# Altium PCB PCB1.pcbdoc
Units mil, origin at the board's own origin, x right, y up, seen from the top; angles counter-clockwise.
Board outline 3779.53 x 2362.2 mil, 2 copper layers (Top Layer, Bottom Layer), stack 62.206 mil thick; 19 components, 19 nets, 99 pads, 0 vias.
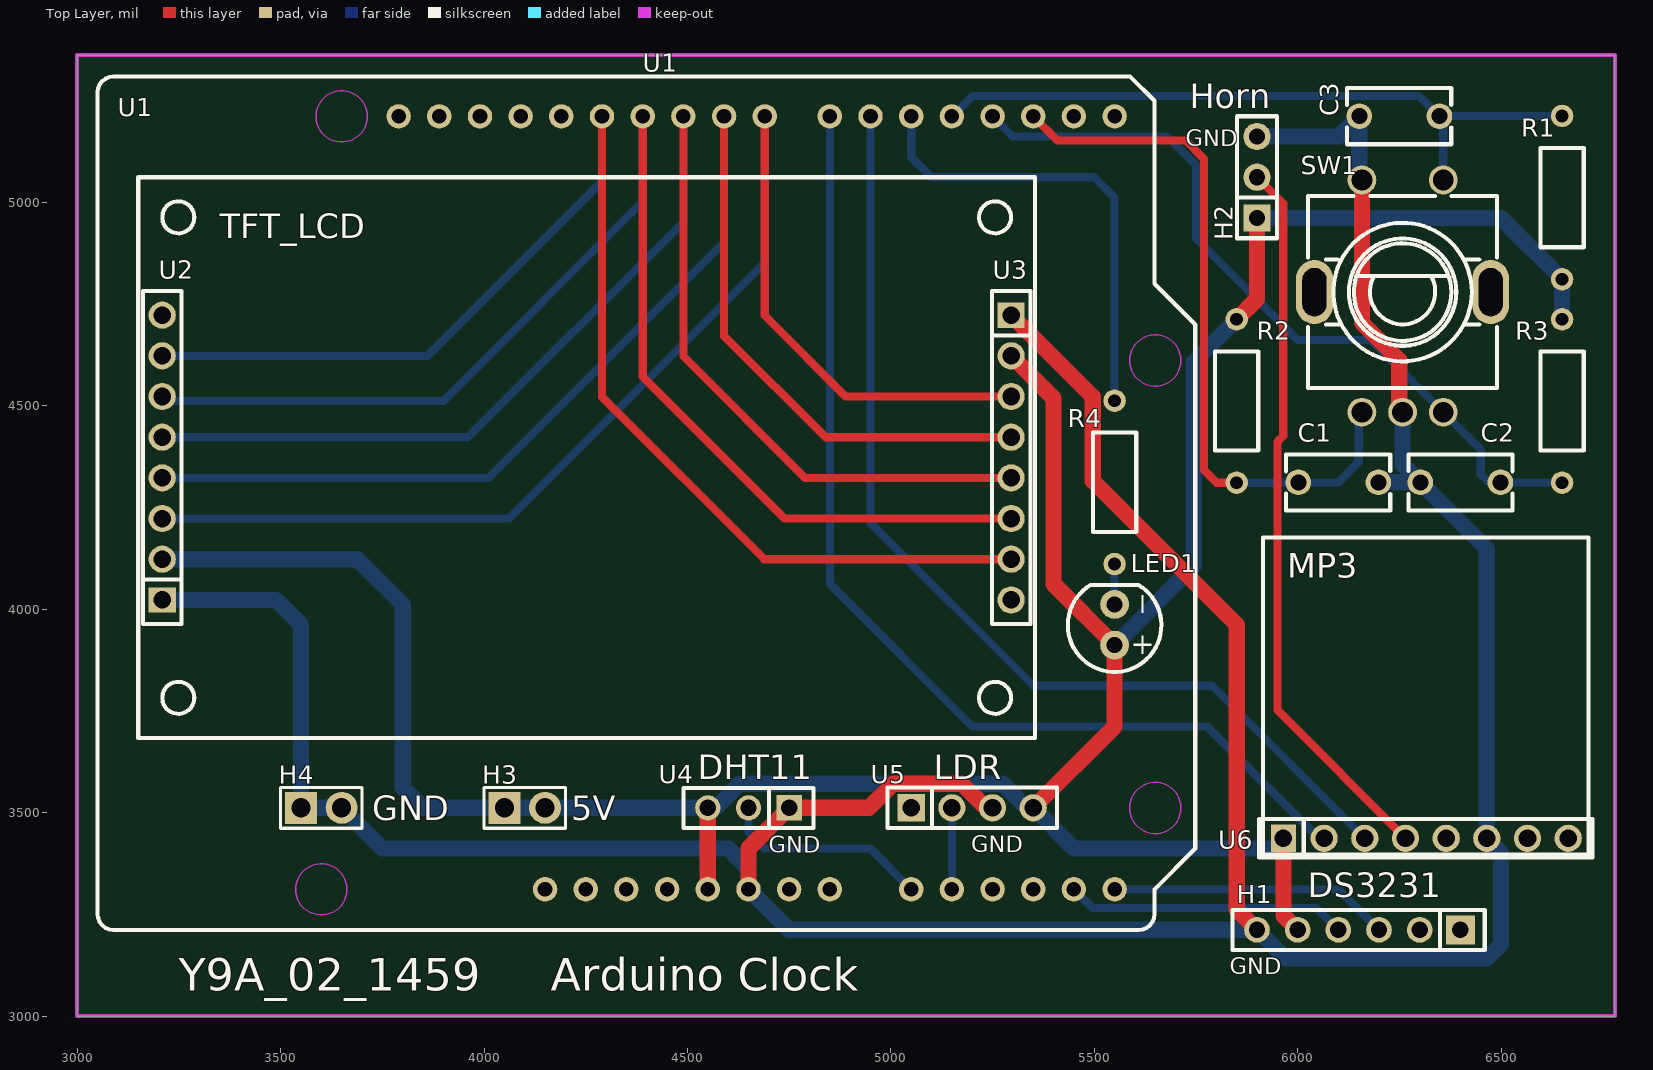
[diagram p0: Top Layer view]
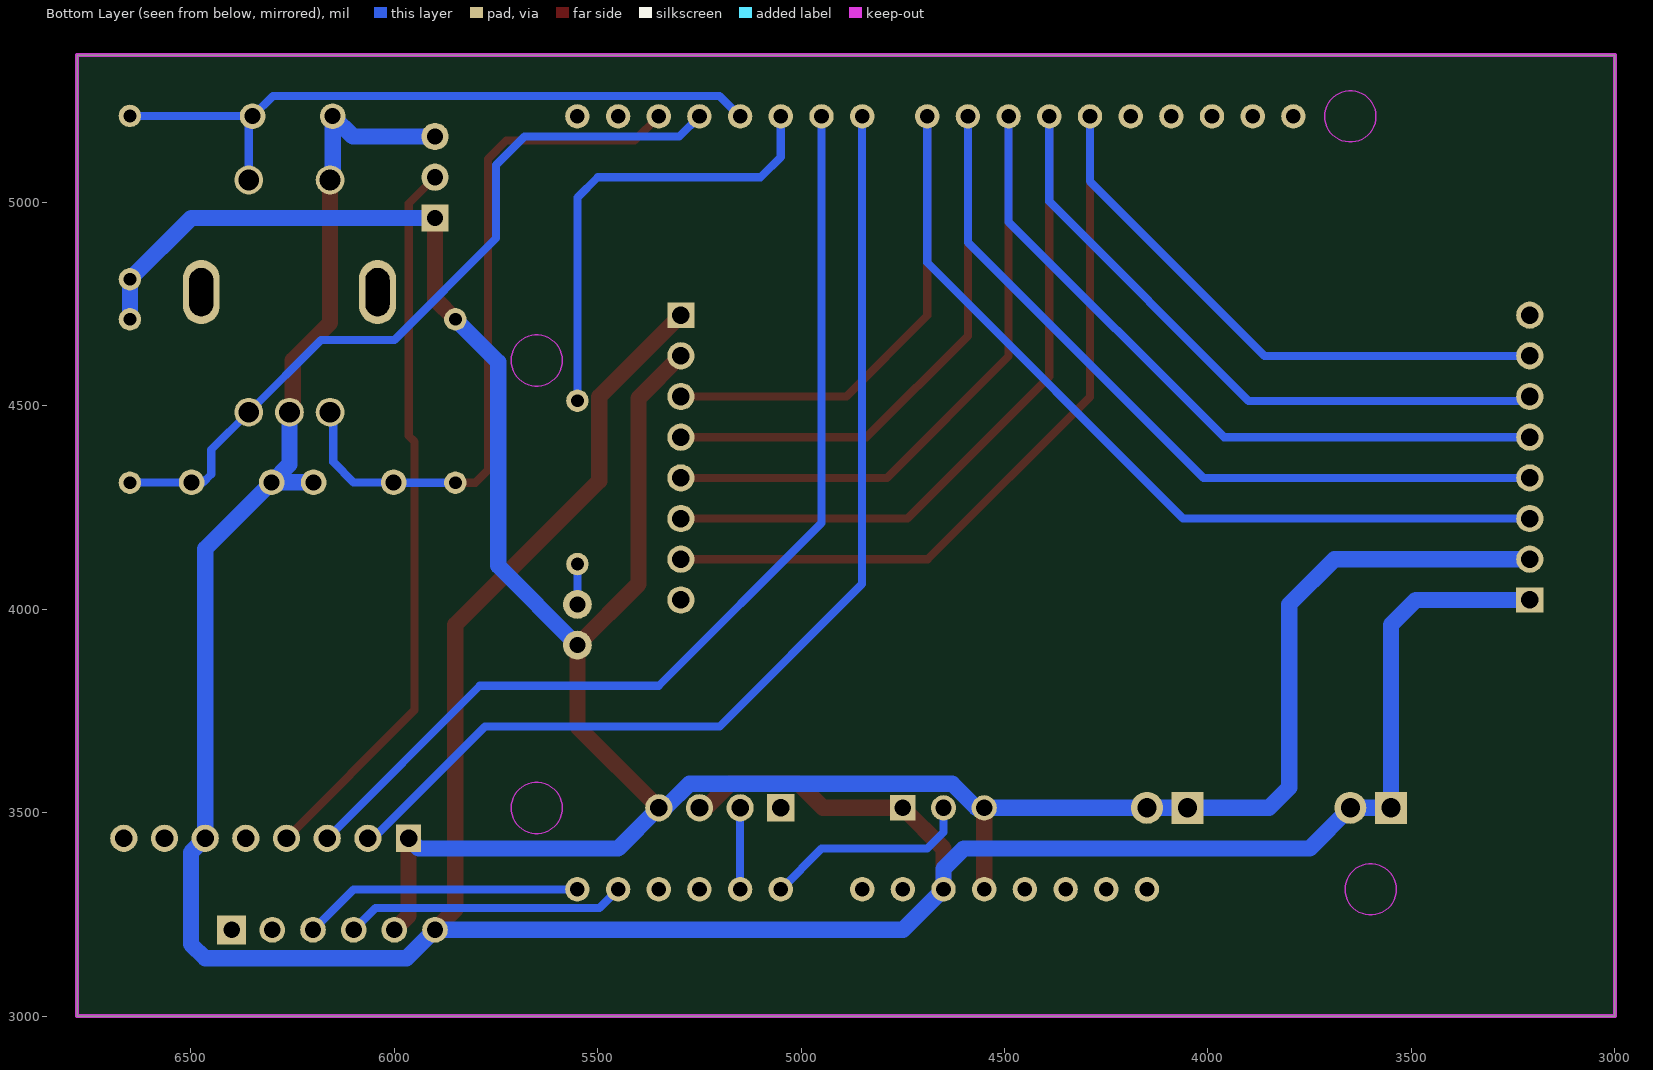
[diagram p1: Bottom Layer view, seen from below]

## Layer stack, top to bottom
Top Solder Mask Layer: solder mask 0.394, Dk 3.3
Top Layer: signal copper 1.379
Dielectric1: surface 59.449, FR4, Dk 4.5
Bottom Layer: signal copper 1.378
Bottom Solder Mask Layer: solder mask 0.394, Dk 3.3

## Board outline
3000,5362.2 6779.53,5362.2 6779.53,3000 3000,3000

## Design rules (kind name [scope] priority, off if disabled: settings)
BoardOutlineClearance copperThickness1oz [All] p0: genericclearance=10 ignorepadtopadclearanceinfootprint=FALSE except(0: Arc-SplitContinuation Track-SplitContinuation SMDPad-SplitContinuation THPad-SplitContinuation Via-SplitContinuation Fill-SplitContinuation Poly-SplitContinuation Region-SplitContinuation Text-SplitContinuation)
BoardOutlineClearance copperThickness2oz [All] p0: genericclearance=10 ignorepadtopadclearanceinfootprint=FALSE except(0: Arc-SplitContinuation Track-SplitContinuation SMDPad-SplitContinuation THPad-SplitContinuation Via-SplitContinuation Fill-SplitContinuation Poly-SplitContinuation Region-SplitContinuation Text-SplitContinuation)
BoardOutlineClearance otherClearance [All] p0: genericclearance=10 ignorepadtopadclearanceinfootprint=FALSE except(0: Arc-SplitContinuation Track-SplitContinuation SMDPad-SplitContinuation THPad-SplitContinuation Via-SplitContinuation Fill-SplitContinuation Poly-SplitContinuation Region-SplitContinuation Text-SplitContinuation)
Clearance copperThickness1oz [All] p1: gap=7 ignorepadtopadclearanceinfootprint=FALSE
Clearance copperThickness2oz [All] p1: gap=7 ignorepadtopadclearanceinfootprint=FALSE
Clearance otherClearance [All] p1: gap=7 ignorepadtopadclearanceinfootprint=FALSE
DiffPairsRouting differentialPair [All] p1: maxuncoupledlength=10 minlimit=6 maxlimit=Infinity mostfreqgap=6 toplayer_minwidth=5 toplayer_prefwidth=10 toplayer_maxwidth=100 bottomlayer_minwidth=5 bottomlayer_prefwidth=10 bottomlayer_maxwidth=100
PasteMaskExpansion pasteMaskExpansion [All] p1: expansion=0
PlaneConnect innerPlane [All] p1: planeconnectstyle=Relief reliefexpansion=20 reliefentries=4 reliefconductorwidth=10 reliefairgap=10
PolygonConnect copperRegion [All] p1: connectstyle=Relief reliefentries=4 reliefconductorwidth=10 polygonreliefangle="90 Angle" airgapwidth=10
RoutingVias viaSize [All] p1: viastyle="Through Hole" holewidth=12.0078 minholewidth=11.811 maxholewidth=248.0314 width=12.0078 minwidth=11.811 maxwidth=248.0314
SolderMaskExpansion solderMaskExpansion [IsVia] p1: useseparateexpansions=TRUE expansion=-1000 expansionbottom=-1000
SolderMaskExpansion solderMaskExpansion [All] p2: useseparateexpansions=TRUE expansion=2 expansionbottom=2
Width copperThickness1oz [All] p1: maxlimit=100 minlimit=5 preferedwidth=10
Width copperThickness2oz [All] p1: maxlimit=100 minlimit=8 preferedwidth=10

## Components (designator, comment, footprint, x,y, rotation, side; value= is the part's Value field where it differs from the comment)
C1 "100nF" CAP-TH_L6.5-W3.5-P5.00-D0.5 6100,4312.2 r180 top
C2 "100nF" CAP-TH_L6.5-W3.5-P5.00-D0.5 6400,4312.2 r0 top
C3 "100nF" CAP-TH_L6.5-W3.5-P5.00-D0.5 6250,5212.2 r180 top
H1 "PM254V-11-06-H85" HDR-TH_6P-P2.54-V-F 6150,3212.2 r180 top
H2 "PZ254V-11-03P" HDR-TH_3P-P2.54-V-M_PZ254V-11-03P 5900,5062.2 r90 top
H3 "PZ254V-11-02P" HDR-TH_2P-P2.54-V-M 4100,3512.2 r0 top
H4 "PZ254V-11-02P" HDR-TH_2P-P2.54-V-M 3600,3512.2 r0 top
LED1 "XL-502SURD" LED-TH_BD5.9-P2.54-RD_RED 5550,3962.2 r270 top
R1 "10kΩ" RES-TH_BD2.7-L6.2-P10.20-D0.4 6650,5012.2 r90 top
R2 "10kΩ" RES-TH_BD2.7-L6.2-P10.20-D0.4 5850,4512.2 r270 top
R3 "10kΩ" RES-TH_BD2.7-L6.2-P10.20-D0.4 6650,4512.2 r270 top
R4 "10kΩ" RES-TH_BD2.7-L6.2-P10.20-D0.4 5550,4312.2 r90 top
SW1 "EC11E15244B2" SW-TH_EC11XXXXXXXX 6257.87,4770.08 r0 top
U1 "" "Arduino UNO" 3050,5312.2 r0 top
U2 "PM254-1-08-Z-8.5" HDR-TH_8P-P2.54-V-F 3209.06,4373.23 r90 top
U3 "PM254-1-08-Z-8.5" HDR-TH_8P-P2.54-V-F 5295.67,4373.23 r270 top
U4 "PM254V-11-03-H85" HDR-TH_3P-P2.54-V-F 4650,3512.2 r180 top
U5 "2.54-1*4P母" HDR-TH_4P-P2.54-V-F 5200,3512.2 r0 top
U6 "PM254-1-08-Z-8.5" HDR-TH_8P-P2.54-V-F 6315,3437.2 r0 top

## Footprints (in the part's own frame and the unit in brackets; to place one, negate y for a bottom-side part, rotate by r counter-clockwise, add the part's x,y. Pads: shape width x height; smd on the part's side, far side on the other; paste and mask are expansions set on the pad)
"Arduino UNO" [mil]
  round 60 hole 36 paste+0 mask+2: 0(2500,-100.4) 1(2400,-100.4) 2(2300,-100.4) 3(2200,-100.4) 4(2100,-100.4) 5(2000,-100.4) 6(1900,-100.4) 7(1800,-100.4) 8(1640,-100.4) 9(1540,-100.4) 10(1440,-100.4) 11(1340,-100.4) 12(1240,-100.4) 13(1140,-100.4) 14(1040,-100.4) 15(940,-100.4) 16(840,-100.4) 17(740,-100.4) 18(1100,-2000.4) 19(1200,-2000.4) 20(1300,-2000.4) 21(1400,-2000.4) 22(1500,-2000.4) 23(1600,-2000.4) 24(1700,-2000.4) 25(1800,-2000.4) 26(2000,-2000.4) 27(2100,-2000.4) 28(2200,-2000.4) 29(2300,-2000.4) 30(2400,-2000.4) 31(2500,-2000.4)
  Board Outline Layer circle w0.1: c550,-2000.4 r62.99
  Board Outline Layer circle w0.1: c600,-100.4 r62.99
  Board Outline Layer circle w0.1: c2600,-700.4 r62.99
  Board Outline Layer circle w0.1: c2600,-1800.4 r62.99
  Board Outline Layer region: 612.99,-2000.4 606.75,-2027.73 589.27,-2049.65 564.02,-2061.81 535.98,-2061.81 510.73,-2049.65 493.25,-2027.73 487.01,-2000.4 487.01,-2000.4 493.25,-1973.07 510.73,-1951.15 535.98,-1938.99 564.02,-1938.99 589.27,-1951.15 606.75,-1973.07 612.99,-2000.4
  Board Outline Layer region: 612.99,-2000.4 606.75,-2027.73 589.27,-2049.65 564.02,-2061.81 535.98,-2061.81 510.73,-2049.65 493.25,-2027.73 487.01,-2000.4 487.01,-2000.4 493.25,-1973.07 510.73,-1951.15 535.98,-1938.99 564.02,-1938.99 589.27,-1951.15 606.75,-1973.07 612.99,-2000.4
  Board Outline Layer region: 662.99,-100.4 656.75,-127.73 639.27,-149.65 614.02,-161.81 585.98,-161.81 560.73,-149.65 543.25,-127.73 537.01,-100.4 537.01,-100.4 543.25,-73.07 560.73,-51.15 585.98,-38.99 614.02,-38.99 639.27,-51.15 656.75,-73.07 662.99,-100.4
  Board Outline Layer region: 662.99,-100.4 656.75,-127.73 639.27,-149.65 614.02,-161.81 585.98,-161.81 560.73,-149.65 543.25,-127.73 537.01,-100.4 537.01,-100.4 543.25,-73.07 560.73,-51.15 585.98,-38.99 614.02,-38.99 639.27,-51.15 656.75,-73.07 662.99,-100.4
  Board Outline Layer region: 2662.99,-700.4 2656.75,-727.73 2639.27,-749.65 2614.02,-761.81 2585.98,-761.81 2560.73,-749.65 2543.25,-727.73 2537.01,-700.4 2537.01,-700.4 2543.25,-673.07 2560.73,-651.15 2585.98,-638.99 2614.02,-638.99 2639.27,-651.15 2656.75,-673.07 2662.99,-700.4
  Board Outline Layer region: 2662.99,-700.4 2656.75,-727.73 2639.27,-749.65 2614.02,-761.81 2585.98,-761.81 2560.73,-749.65 2543.25,-727.73 2537.01,-700.4 2537.01,-700.4 2543.25,-673.07 2560.73,-651.15 2585.98,-638.99 2614.02,-638.99 2639.27,-651.15 2656.75,-673.07 2662.99,-700.4
  Board Outline Layer region: 2662.99,-1800.4 2656.75,-1827.73 2639.27,-1849.65 2614.02,-1861.81 2585.98,-1861.81 2560.73,-1849.65 2543.25,-1827.73 2537.01,-1800.4 2537.01,-1800.4 2543.25,-1773.07 2560.73,-1751.15 2585.98,-1738.99 2614.02,-1738.99 2639.27,-1751.15 2656.75,-1773.07 2662.99,-1800.4
  Board Outline Layer region: 2662.99,-1800.4 2656.75,-1827.73 2639.27,-1849.65 2614.02,-1861.81 2585.98,-1861.81 2560.73,-1849.65 2543.25,-1827.73 2537.01,-1800.4 2537.01,-1800.4 2543.25,-1773.07 2560.73,-1751.15 2585.98,-1738.99 2614.02,-1738.99 2639.27,-1751.15 2656.75,-1773.07 2662.99,-1800.4
  silkscreen extent 0,-2100 2698,-2
CAP-TH_L6.5-W3.5-P5.00-D0.5 [mm]
  round 1.6 hole 1: 1(-2.499,0) 2(2.499,0)
  silkscreen extent -3.24,-1.75 3.26,1.75
HDR-TH_2P-P2.54-V-M [mm]
  rect 2x2 hole 1.2: 1(-1.27,0)
  round 2 hole 1.2: 2(1.27,0)
  silkscreen extent -2.54,-1.27 2.54,1.27
HDR-TH_3P-P2.54-V-F [mil]
  rect 62x62 hole 40.16: 1(-100,0)
  round 62 hole 40.16: 2(0,0) 3(100,0)
  silkscreen extent -160,-49 160,49
HDR-TH_3P-P2.54-V-M_PZ254V-11-03P [mm]
  rect 1.7x1.7 hole 1.02: 1(-2.54,0)
  round 1.7 hole 1.02: 2(0,0) 3(2.54,0)
  silkscreen extent -3.81,-1.25 3.81,1.25
HDR-TH_4P-P2.54-V-F [mm]
  rect 1.7x1.7 hole 1.1: 1(-3.81,0)
  round 1.7 hole 1.1: 2(-1.27,0) 3(1.27,0) 4(3.81,0)
  silkscreen extent -5.29,-1.27 5.29,1.27
HDR-TH_6P-P2.54-V-F [mm]
  rect 1.8x1.8 hole 1.02: 1(-6.35,0)
  round 1.6 hole 1.02: 2(-3.81,0) 3(-1.27,0) 4(1.27,0) 5(3.81,0) 6(6.35,0)
  silkscreen extent -7.87,-1.25 7.87,1.25
HDR-TH_8P-P2.54-V-F [mm]
  rect 1.575x1.7 hole 1.1: 1(-8.89,0)
  round 1.7 hole 1.1: 2(-6.35,0) 3(-3.81,0) 4(-1.27,0) 5(1.27,0) 6(3.81,0) 7(6.35,0) 8(8.89,0)
  silkscreen extent -10.4,-1.2 10.4,1.2
LED-TH_BD5.9-P2.54-RD_RED [mm]
  round 1.8 hole 1 paste+0 mask+0.05: 1(-1.27,0) 2(1.27,0)
  silkscreen extent -2.49,-2.92 2.94,2.92
RES-TH_BD2.7-L6.2-P10.20-D0.4 [mm]
  round 1.4 hole 0.8 copper offset 0,0: 1(-5.1,0) 2(5.1,0)
  silkscreen extent -3.1,-1.35 3.1,1.35
SW-TH_EC11XXXXXXXX [mm]
  oval 2.3x4 hole 1.5 slot 3 at 90 deg: 6(5.5,0.25) 7(-5.5,0.25)
  round 1.8 hole 1.3: A(-2.54,-7.25) B(2.54,-7.25) C(0,-7.25) D(-2.54,7.25) E(2.54,7.25)
  silkscreen extent -5.9,-5.75 5.9,6.25

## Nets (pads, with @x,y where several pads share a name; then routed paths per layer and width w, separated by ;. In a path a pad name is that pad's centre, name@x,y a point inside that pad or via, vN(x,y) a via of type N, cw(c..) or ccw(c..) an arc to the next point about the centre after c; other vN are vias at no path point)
$1N118: H2.2 U6.4 | length 1788.2
  Top Layer w20: H2.2 5964.45,4997.76 5964.45,4426.65 5950,4412.2 5950,3752.2 U6.4
$1N130: LED1.1 R4.1 | length 99.2
  Bottom Layer w20: LED1.1 R4.1
+5V: H1.5 H2.1 H3.1 H3.2 LED1.2 R1.1 R2.1 R3.1 U1.22 U2.2 U3.2 U4.3 U5.4 U6.1 | length 7218.6
  Top Layer w40: U1.22 U4.3 ; U3.2 5400,4518.9 5400,4062.2 LED1.2 5550,3712.2 U5.4 ; R2.1 5900,4762.99 H2.1 ; U6.1 5965,3247.2 H1.5
  Bottom Layer w40: U2.2 3688.98,4123.23 3800,4012.2 3800,3562.2 3850,3512.2 H3.1 H3.2 U4.3 4569.41,3512.2 4628.86,3571.65 5274.62,3571.65 5334.07,3512.2 U5.4 5450,3412.2 5940,3412.2 U6.1 ; LED1.2 5744.8,4107.01 5744.8,4607.8 R2.1 ; H2.1 6499.21,4962.2 R1.1 R3.1
CLOCK_SCL: H1.3 U1.31 | length 691.3
  Bottom Layer w20: U1.31 5600,3311.8 6100.4,3311.8 H1.3
CLOCK_SDA: H1.4 U1.30 | length 691.3
  Bottom Layer w20: U1.30 5495.98,3265.82 6046.38,3265.82 H1.4
DHT11: U1.26 U4.2 | length 518.2
  Bottom Layer w20: U4.2 4650,3452.2 4690,3412.2 4949.6,3412.2 U1.26
EC11_A: C1.2 R2.2 SW1.A U1.2 | length 1767.8
  Top Layer w20: U1.2 5409.6,5152.2 5725,5152.2 5770,5107.2 5770,4342.2 5800.79,4311.41 R2.2
  Bottom Layer w20: R2.2 6000.81,4311.41 C1.2 6100,4312.2 6150,4362.2 6150,4476.77 SW1.A
EC11_B: C2.2 R3.2 SW1.B U1.3 | length 1913.9
  Bottom Layer w20: U1.3 5299.6,5162.2 5680.31,5162.2 5750,5092.51 5750,4912.2 6000,4662.2 6180.31,4662.2 SW1.B 6450,4392.51 6450,4332.2 6470,4312.2 C2.2 6649.21,4312.2 R3.2
EC11_C: C3.1 R1.2 SW1.E U1.4 | length 1702.5
  Bottom Layer w20: U1.4 5200.4,5262.2 6298.4,5262.2 C3.1 ; SW1.E 6357.87,5202.74 C3.1 ; R1.2 6349.19,5212.99 C3.1
GND: C1.1 C2.1 C3.2 H1.6 H2.3 H4.1 H4.2 SW1.C SW1.D U1.23 U2.1 U3.1 U4.1 U5.3 U6.6 | length 9070.7
  Top Layer w40: U1.23 4650,3412.2 U4.1 4946.32,3512.2 5005.77,3571.65 5174.62,3571.65 5234.07,3512.2 U5.3 ; U3.1 5496.46,4522.44 5496.46,4315.75 5850,3962.2 5850,3262.2 H1.6 ; SW1.D 6157.87,4704.34 6250,4612.2 6250,4492.51 SW1.C
  Bottom Layer w40: U2.1 3488.98,4023.23 3550,3962.2 H4.1 H4.2 3750,3412.2 4600,3412.2 4650,3362.2 U1.23 4749.6,3212.2 H1.6 5970,3142.2 6465,3142.2 6500,3177.2 6500,3402.2 U6.6 6465,4148.8 C2.1 ; H2.3 6101.6,5162.2 C3.2 6151.6,5061.78 SW1.D ; C1.1 C2.1 ; SW1.C 6257.87,4355.94 C2.1
LCD_CS: U1.12 U2.7 U3.7 | length 3278.8
  Top Layer w20: U1.12 4290,4522.2 4688.98,4123.23 U3.7
  Bottom Layer w20: U2.7 3861.02,4623.23 4290,5052.2 U1.12
LCD_DC: U1.11 U2.6 U3.6 | length 3287.9
  Top Layer w20: U1.11 4390,4572.2 4738.98,4223.23 U3.6
  Bottom Layer w20: U2.6 3220.08,4512.2 3900,4512.2 4390,5002.2 U1.11
LCD_RES: U1.10 U2.5 U3.5 | length 3278.8
  Top Layer w20: U1.10 4490,4622.2 4788.98,4323.23 U3.5
  Bottom Layer w20: U2.5 3961.02,4423.23 4490,4952.2 U1.10
LCD_SCL: U1.8 U2.3 U3.3 | length 3278.8
  Top Layer w20: U1.8 4690,4722.2 4888.98,4523.23 U3.3
  Bottom Layer w20: U2.3 4061.02,4223.23 4690,4852.2 U1.8
LCD_SDA: U1.9 U2.4 U3.4 | length 3278.8
  Top Layer w20: U1.9 4590,4672.2 4838.98,4423.23 U3.4
  Bottom Layer w20: U2.4 4011.02,4323.23 4590,4902.2 U1.9
LDR: U1.27 U5.2 | length 200.4
  Bottom Layer w20: U1.27 U5.2
LED: R4.2 U1.5 | length 1140.2
  Bottom Layer w20: U1.5 5050,5112.2 5100,5062.2 5500,5062.2 5550,5012.2 R4.2
MP3_RX: U1.7 U6.2 | length 2623.5
  Bottom Layer w20: U1.7 4850,4062.2 5200,3712.2 5777.07,3712.2 6052.07,3437.2 U6.2
MP3_TX: U1.6 U6.3 | length 2535.6
  Bottom Layer w20: U1.6 4950,4212.2 5350,3812.2 5790,3812.2 U6.3
pads on no net: H1.1 H1.2 SW1.6 SW1.7 U1.0 U1.1 U1.13 U1.14 U1.15 U1.16 U1.17 U1.18 U1.19 U1.20 U1.21 U1.24 U1.25 U1.28 U1.29 U2.8 U3.8 U5.1 U6.5 U6.7 U6.8

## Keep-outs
Board Outline Layer:
  the board outline again, w10

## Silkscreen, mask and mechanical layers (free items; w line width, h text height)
Top Silkscreen Layer:
  circle w10: c3248.43,4963.78 r39.37
  circle w10: c3248.43,3782.68 r39.37
  circle w10: c5256.3,4963.78 r39.37
  circle w10: c5256.3,3782.68 r39.37
  lines w10: 3150,3684.25 5354.72,3684.25 5354.72,5062.2 3150,5062.2 3150,3684.25 ; 5915,3397.2 6715,3397.2 6715,4177.2 5915,4177.2 5915,3397.2
  text "Horn" at 5735,5232.2 h60
  text "GND" at 5725.48,5138.2 h40
  text "TFT_LCD" at 3350,4912.2 h60
  text "MP3" at 5975,4077.2 h60
  text "DHT11" at 4525,3582.2 h60
  text "LDR" at 5105,3582.2 h60
  text "GND" at 3725,3482.2 h60
  text "5V" at 4215,3482.2 h60
  text "GND" at 5197.65,3403.2 h40
  text "GND" at 4700,3402.2 h40
  text "DS3231" at 6025,3292.2 h60
  text "GND" at 5832.65,3103.2 h40
  text "Y9A_02_1459     Arduino Clock" at 3250,3062.2 h80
